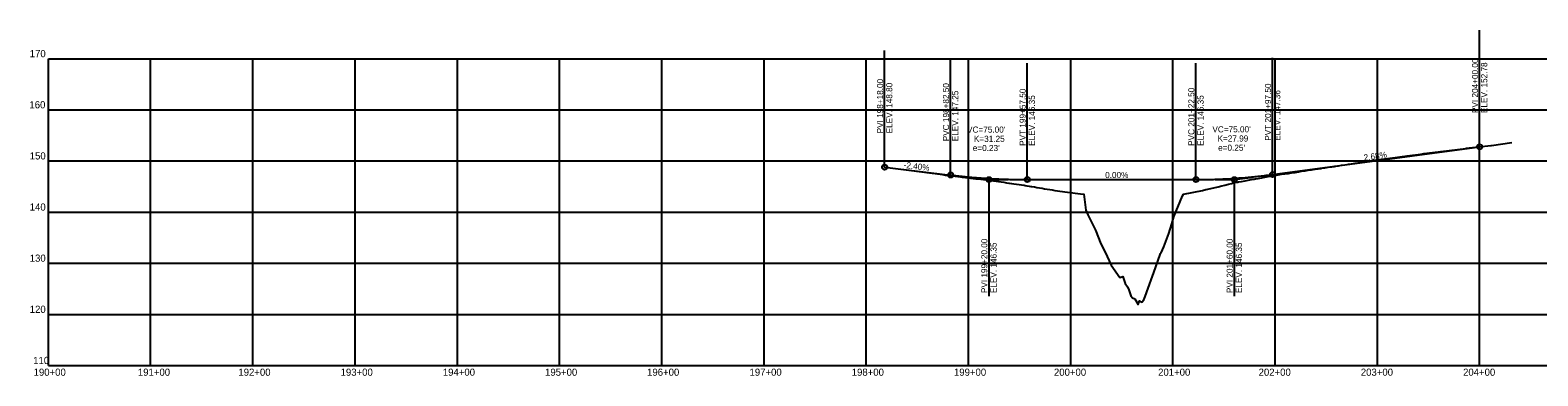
# Model space of a CAD drawing. Extents: x 1556849 to 1559393, y 1802592 to 1804749.
# Drawn here: x 1556849 to 1558324, y 1802592 to 1802930 of the extents above; entities that cross this region are included whole.
import ezdxf

# ---------------------------------------------------------------- set-up
doc = ezdxf.new("R2010")
doc.units = 0
for name, color, linetype in [('R_Axis', 7, 'Continuous'), ('R_Axis Annot', 7, 'Continuous'), ('R_Exist Surface', 7, 'Continuous'), ('R_Grid', 7, 'Continuous'), ('R_Vert Alg', 7, 'Continuous'), ('R_Vert Alg Annot', 7, 'Continuous')]:
    doc.layers.add(name, color=color, linetype=linetype)

msp = doc.modelspace()

# ---------------------------------------------------------------- linework, layer by layer
at = {"layer": 'R_Axis'}
for q in [(1556867.2, 1802901.7), (1558567.2, 1802601.7)]:
    msp.add_line((1556867.2, 1802601.7), q, dxfattribs=at)
at = {"layer": 'R_Exist Surface'}
msp.add_lwpolyline([(1557684.5, 1802795.8), (1557685.5, 1802795.7), (1557708.7, 1802792.7), (1557731.7, 1802789.8), (1557732, 1802789.7), (1557741.8, 1802788.4), (1557744.3, 1802788), (1557745.6, 1802787.9), (1557746.7, 1802787.8), (1557746.8, 1802787.8), (1557749.3, 1802787.4), (1557751.8, 1802787.1), (1557754.3, 1802786.8), (1557756.8, 1802786.5), (1557759.3, 1802786.2), (1557760.6, 1802786.1), (1557761.4, 1802786), (1557761.8, 1802786), (1557762.3, 1802785.9), (1557764.3, 1802785.6), (1557766.8, 1802785.3), (1557769.3, 1802785), (1557771.8, 1802784.7), (1557774.3, 1802784.4), (1557776.8, 1802784.2), (1557776.9, 1802784.1), (1557779.3, 1802783.9), (1557781.8, 1802783.6), (1557784.3, 1802783.3), (1557786.8, 1802783.1), (1557787.5, 1802783), (1557789.3, 1802782.7), (1557791.8, 1802782.4), (1557792.3, 1802782.3), (1557794.3, 1802782.1), (1557795.9, 1802781.9), (1557796.8, 1802781.8), (1557799.3, 1802781.3), (1557801.8, 1802780.9), (1557804.3, 1802780.5), (1557806.8, 1802780.1), (1557807.3, 1802780), (1557809.3, 1802779.8), (1557809.6, 1802779.8), (1557811.7, 1802779.4), (1557814.2, 1802779.1), (1557816.7, 1802778.7), (1557819.2, 1802778.3), (1557821.7, 1802778), (1557822.5, 1802777.8), (1557824.2, 1802777.5), (1557826.7, 1802777.1), (1557828.2, 1802776.9), (1557829.2, 1802776.7), (1557831.7, 1802776.3), (1557834.2, 1802775.8), (1557836.7, 1802775.4), (1557839.2, 1802775), (1557841.7, 1802774.5), (1557841.8, 1802774.5), (1557844.2, 1802774.2), (1557846.7, 1802773.8), (1557849.2, 1802773.4), (1557850.4, 1802773.2), (1557851.7, 1802773), (1557854.2, 1802772.6), (1557856.7, 1802772.2), (1557859.2, 1802771.8), (1557861.4, 1802771.4), (1557879.5, 1802769.3), (1557879.9, 1802769.3), (1557879.9, 1802769.2), (1557881.9, 1802753.7), (1557883.8, 1802749.1), (1557885.9, 1802745.3), (1557891.4, 1802734.2), (1557896.7, 1802720.7), (1557900.9, 1802712.5), (1557906.7, 1802700), (1557915.1, 1802687.7), (1557918.3, 1802688.6), (1557920.4, 1802681.8), (1557922.6, 1802678.7), (1557924.1, 1802675.7), (1557926.1, 1802669.9), (1557927.7, 1802668), (1557929.8, 1802666.8), (1557933.2, 1802661.3), (1557934.6, 1802665), (1557936.8, 1802663.7), (1557938.6, 1802666.1), (1557940.2, 1802669.3), (1557950.2, 1802697.2), (1557955, 1802711.4), (1557955.6, 1802711.8), (1557958.2, 1802717.8), (1557963.2, 1802730.8), (1557966.1, 1802740.1), (1557968.1, 1802747.1), (1557976.6, 1802767.6), (1557977.4, 1802769.3), (1557996, 1802772.7), (1557999.3, 1802773.7), (1558001.5, 1802774.1), (1558011.6, 1802776.6), (1558014.9, 1802777.4), (1558014.9, 1802777.4), (1558018.1, 1802778.2), (1558021.4, 1802779), (1558024.6, 1802779.8), (1558027.9, 1802780.6), (1558028, 1802780.6), (1558030.7, 1802781.1), (1558031.2, 1802781.2), (1558034.4, 1802781.8), (1558037.7, 1802782.4), (1558040.9, 1802783), (1558044.2, 1802783.6), (1558046.5, 1802784), (1558047.5, 1802784.2), (1558047.5, 1802784.2), (1558048.3, 1802784.3), (1558050.7, 1802784.7), (1558054, 1802785.3), (1558057.2, 1802785.9), (1558060.5, 1802786.4), (1558063.8, 1802786.9), (1558064.5, 1802787.1), (1558066.2, 1802787.4), (1558067, 1802787.6), (1558070.3, 1802788.1), (1558073.3, 1802788.7), (1558073.5, 1802788.7), (1558076.8, 1802789.2), (1558080.1, 1802789.6), (1558083.3, 1802790.1), (1558086.6, 1802790.6), (1558087.1, 1802790.7), (1558088.4, 1802790.9), (1558089.9, 1802791.1), (1558090.4, 1802791.2), (1558093.1, 1802791.6), (1558096.4, 1802792.1), (1558099.6, 1802792.6), (1558102.9, 1802793.1), (1558106.2, 1802793.6), (1558109.4, 1802794.1), (1558112.1, 1802794.5), (1558112.4, 1802794.6), (1558112.7, 1802794.6), (1558115.9, 1802795.1), (1558119.2, 1802795.6), (1558122.5, 1802796), (1558124.8, 1802796.4), (1558125.7, 1802796.5), (1558126.5, 1802796.6), (1558129, 1802797), (1558132.2, 1802797.5), (1558135.5, 1802797.9), (1558137.6, 1802798.3), (1558138.8, 1802798.5), (1558142, 1802799), (1558145.3, 1802799.5), (1558148.5, 1802800), (1558148.8, 1802800), (1558150.4, 1802800.3), (1558151.8, 1802800.5), (1558155.1, 1802801), (1558158.3, 1802801.6), (1558161.6, 1802802.1), (1558163, 1802802.4), (1558163.1, 1802802.4), (1558179.6, 1802804.6), (1558179.6, 1802804.6), (1558196.2, 1802806.8), (1558196.2, 1802806.8), (1558209.6, 1802808.5), (1558212.7, 1802808.9), (1558212.7, 1802808.9), (1558229.3, 1802811.1), (1558229.3, 1802811.1), (1558253.8, 1802814), (1558254, 1802814.1), (1558254.2, 1802814.1), (1558278.3, 1802817), (1558278.7, 1802817), (1558298.7, 1802819.8)], dxfattribs=at)
at = {"layer": 'R_Grid'}
for p, q in [((1556867.2, 1802901.7), (1558567.2, 1802901.7)), ((1556867.2, 1802901.7), (1558567.2, 1802901.7)), ((1556967.2, 1802601.7), (1556967.2, 1802901.7)), ((1557067.2, 1802601.7), (1557067.2, 1802901.7)), ((1557167.2, 1802601.7), (1557167.2, 1802901.7)), ((1557267.2, 1802601.7), (1557267.2, 1802901.7)), ((1557367.2, 1802601.7), (1557367.2, 1802901.7)), ((1557467.2, 1802601.7), (1557467.2, 1802901.7)), ((1557567.2, 1802601.7), (1557567.2, 1802901.7)), ((1557667.2, 1802601.7), (1557667.2, 1802901.7)), ((1557767.2, 1802601.7), (1557767.2, 1802901.7)), ((1557867.2, 1802601.7), (1557867.2, 1802901.7)), ((1557967.2, 1802601.7), (1557967.2, 1802901.7)), ((1558067.2, 1802601.7), (1558067.2, 1802901.7)), ((1558167.2, 1802601.7), (1558167.2, 1802901.7)), ((1558267.2, 1802601.7), (1558267.2, 1802901.7)), ((1556867.2, 1802851.7), (1558567.2, 1802851.7)), ((1556867.2, 1802801.7), (1558567.2, 1802801.7)), ((1556867.2, 1802751.7), (1558567.2, 1802751.7)), ((1556867.2, 1802701.7), (1558567.2, 1802701.7)), ((1556867.2, 1802651.7), (1558567.2, 1802651.7))]:
    msp.add_line(p, q, dxfattribs=at)
at = {"layer": 'R_Vert Alg'}
for p, q in [((1558064.7, 1802788.5), (1558267.2, 1802815.6)), ((1557685.2, 1802795.7), (1557749.7, 1802788)), ((1557824.7, 1802783.5), (1557989.7, 1802783.5))]:
    msp.add_line(p, q, dxfattribs=at)
for points in [[(1557989.7, 1802783.5), (1557991.2, 1802783.5), (1557992.8, 1802783.5), (1557994.4, 1802783.5), (1557995.9, 1802783.5), (1557997.5, 1802783.5), (1557999.1, 1802783.6), (1558000.6, 1802783.6), (1558002.2, 1802783.6), (1558003.7, 1802783.7), (1558005.3, 1802783.7), (1558006.9, 1802783.7), (1558008.4, 1802783.8), (1558010, 1802783.8), (1558011.6, 1802783.9), (1558013.1, 1802784), (1558014.7, 1802784), (1558016.2, 1802784.1), (1558017.8, 1802784.2), (1558019.4, 1802784.3), (1558020.9, 1802784.4), (1558022.5, 1802784.4), (1558024.1, 1802784.5), (1558025.6, 1802784.6), (1558028.7, 1802784.8), (1558030.3, 1802785), (1558031.9, 1802785.1), (1558033.4, 1802785.2), (1558035, 1802785.3), (1558036.6, 1802785.4), (1558038.1, 1802785.6), (1558039.7, 1802785.7), (1558041.2, 1802785.9), (1558042.8, 1802786), (1558044.4, 1802786.2), (1558045.9, 1802786.3), (1558047.5, 1802786.5), (1558049.1, 1802786.6), (1558050.6, 1802786.8), (1558052.2, 1802787), (1558053.7, 1802787.1), (1558055.3, 1802787.3), (1558056.9, 1802787.5), (1558058.4, 1802787.7), (1558060, 1802787.9), (1558061.6, 1802788.1), (1558063.1, 1802788.3), (1558064.7, 1802788.5)], [(1557749.7, 1802788), (1557751.2, 1802787.8), (1557752.8, 1802787.6), (1557754.4, 1802787.4), (1557755.9, 1802787.3), (1557757.5, 1802787.1), (1557759.1, 1802786.9), (1557760.6, 1802786.8), (1557762.2, 1802786.6), (1557763.7, 1802786.5), (1557765.3, 1802786.3), (1557766.9, 1802786.2), (1557768.4, 1802786), (1557770, 1802785.9), (1557771.6, 1802785.7), (1557773.1, 1802785.6), (1557774.7, 1802785.5), (1557776.2, 1802785.4), (1557777.8, 1802785.2), (1557779.4, 1802785.1), (1557780.9, 1802785), (1557782.5, 1802784.9), (1557784.1, 1802784.8), (1557785.6, 1802784.7), (1557788.7, 1802784.5), (1557790.3, 1802784.4), (1557791.9, 1802784.3), (1557793.4, 1802784.3), (1557795, 1802784.2), (1557796.6, 1802784.1), (1557798.1, 1802784), (1557799.7, 1802784), (1557801.2, 1802783.9), (1557802.8, 1802783.9), (1557804.4, 1802783.8), (1557805.9, 1802783.8), (1557807.5, 1802783.7), (1557809.1, 1802783.7), (1557810.6, 1802783.6), (1557812.2, 1802783.6), (1557813.7, 1802783.6), (1557815.3, 1802783.5), (1557816.9, 1802783.5), (1557818.4, 1802783.5), (1557820, 1802783.5), (1557821.6, 1802783.5), (1557823.1, 1802783.5), (1557824.7, 1802783.5)]]:
    msp.add_lwpolyline(points, dxfattribs=at)
at = {"layer": 'R_Vert Alg Annot'}
for p, q in [((1558267.2, 1802845.6), (1558267.2, 1802929.6)), ((1557685.2, 1802825.7), (1557685.2, 1802909.7)), ((1557749.7, 1802818), (1557749.7, 1802902)), ((1557824.7, 1802813.5), (1557824.7, 1802897.5)), ((1557989.7, 1802813.5), (1557989.7, 1802897.5)), ((1558064.7, 1802818.5), (1558064.7, 1802902.5)), ((1558267.2, 1802815.6), (1558267.2, 1802845.6)), ((1557685.2, 1802795.7), (1557685.2, 1802825.7)), ((1557749.7, 1802788), (1557749.7, 1802818)), ((1558064.7, 1802788.5), (1558064.7, 1802818.5)), ((1557824.7, 1802783.5), (1557824.7, 1802813.5)), ((1557989.7, 1802783.5), (1557989.7, 1802813.5)), ((1557768.4, 1802785.7), (1557787.2, 1802783.5)), ((1557787.2, 1802783.5), (1557805.9, 1802783.5)), ((1557787.2, 1802783.5), (1557787.2, 1802753.5)), ((1558008.4, 1802783.5), (1558027.2, 1802783.5)), ((1558027.2, 1802783.5), (1558045.9, 1802786)), ((1558027.2, 1802783.5), (1558027.2, 1802753.5)), ((1557787.2, 1802753.5), (1557787.2, 1802669.5)), ((1558027.2, 1802753.5), (1558027.2, 1802669.5))]:
    msp.add_line(p, q, dxfattribs=at)
for centre in [(1558267.2, 1802815.6), (1557685.2, 1802795.7), (1557749.7, 1802788), (1558064.7, 1802788.5), (1557787.2, 1802783.5), (1557824.7, 1802783.5), (1557989.7, 1802783.5), (1558027.2, 1802783.5)]:
    msp.add_circle(centre, 2.5, dxfattribs=at)

# ---------------------------------------------------------------- texts
at = {"layer": 'R_Axis Annot'}
for s, height, p in [('170', 7, (1556848.9, 1802903.2)), ('170', 7, (1556848.9, 1802903.2)), ('160', 7, (1556848.6, 1802853.2)), ('150', 7, (1556848.9, 1802803.2)), ('140', 7, (1556848.9, 1802753.2)), ('130', 7, (1556848.9, 1802703.2)), ('120', 7, (1556848.9, 1802653.2)), ('110', 7, (1556852.3, 1802603.2)), ('190+00', 7, (1556852.7, 1802591.7)), ('-', 0.0001, (1556867.2, 1802601.7)), ('191+00', 7, (1556954.7, 1802591.7)), ('192+00', 7, (1557053, 1802591.7)), ('193+00', 7, (1557153, 1802591.7)), ('194+00', 7, (1557253, 1802591.7)), ('195+00', 7, (1557353, 1802591.7)), ('196+00', 7, (1557452.8, 1802591.7)), ('197+00', 7, (1557553, 1802591.7)), ('198+00', 7, (1557653, 1802591.7)), ('199+00', 7, (1557753, 1802591.7)), ('200+00', 7, (1557850.8, 1802591.7)), ('201+00', 7, (1557952.7, 1802591.7)), ('202+00', 7, (1558051, 1802591.7)), ('203+00', 7, (1558151, 1802591.7)), ('204+00', 7, (1558251, 1802591.7))]:
    msp.add_text(s, height=height, dxfattribs=at).set_placement(p)
at = {"layer": 'R_Vert Alg Annot'}
for s, rotation, p in [('PVI 204+00.00', 90, (1558265.7, 1802848.6)), ('ELEV. 152.78', 90, (1558274.7, 1802848.6)), ('PVI 198+18.00', 90, (1557683.7, 1802828.7)), ('ELEV. 148.80', 90, (1557692.7, 1802828.7)), ('PVC 198+82.50', 90, (1557748.2, 1802821)), ('PVT 201+97.50', 90, (1558063.2, 1802821.5)), ('ELEV. 147.25', 90, (1557757.2, 1802821)), ('PVT 199+57.50', 90, (1557823.2, 1802816.5)), ('ELEV. 146.35', 90, (1557832.2, 1802816.5)), ('PVC 201+22.50', 90, (1557988.2, 1802816.5)), ('ELEV. 146.35', 90, (1557997.2, 1802816.5)), ('ELEV. 147.36', 90, (1558072.2, 1802821.5)), ('2.68%', 7.631, (1558154.2, 1802802)), ('-2.40%', 353.1572, (1557703.5, 1802795)), ('0.00%', 360, (1557900.9, 1802785)), ('PVI 199+20.00', 90, (1557785.7, 1802672.5)), ('ELEV. 146.35', 90, (1557794.7, 1802672.5)), ('PVI 201+60.00', 90, (1558025.7, 1802672.5)), ('ELEV. 146.35', 90, (1558034.7, 1802672.5))]:
    msp.add_text(s, height=6, rotation=rotation, dxfattribs=at).set_placement(p)
for s, p in [("VC=75.00'", (1557765.8, 1802829.4)), ("VC=75.00'", (1558005.8, 1802829.7)), ('K=31.25', (1557772.5, 1802820.4)), ('K=27.99', (1558010.8, 1802820.7)), ("e=0.25'", (1558011.4, 1802811.7)), ("e=0.23'", (1557771.4, 1802811.4))]:
    msp.add_text(s, height=6, dxfattribs=at).set_placement(p)

doc.saveas('drawing.dxf')
